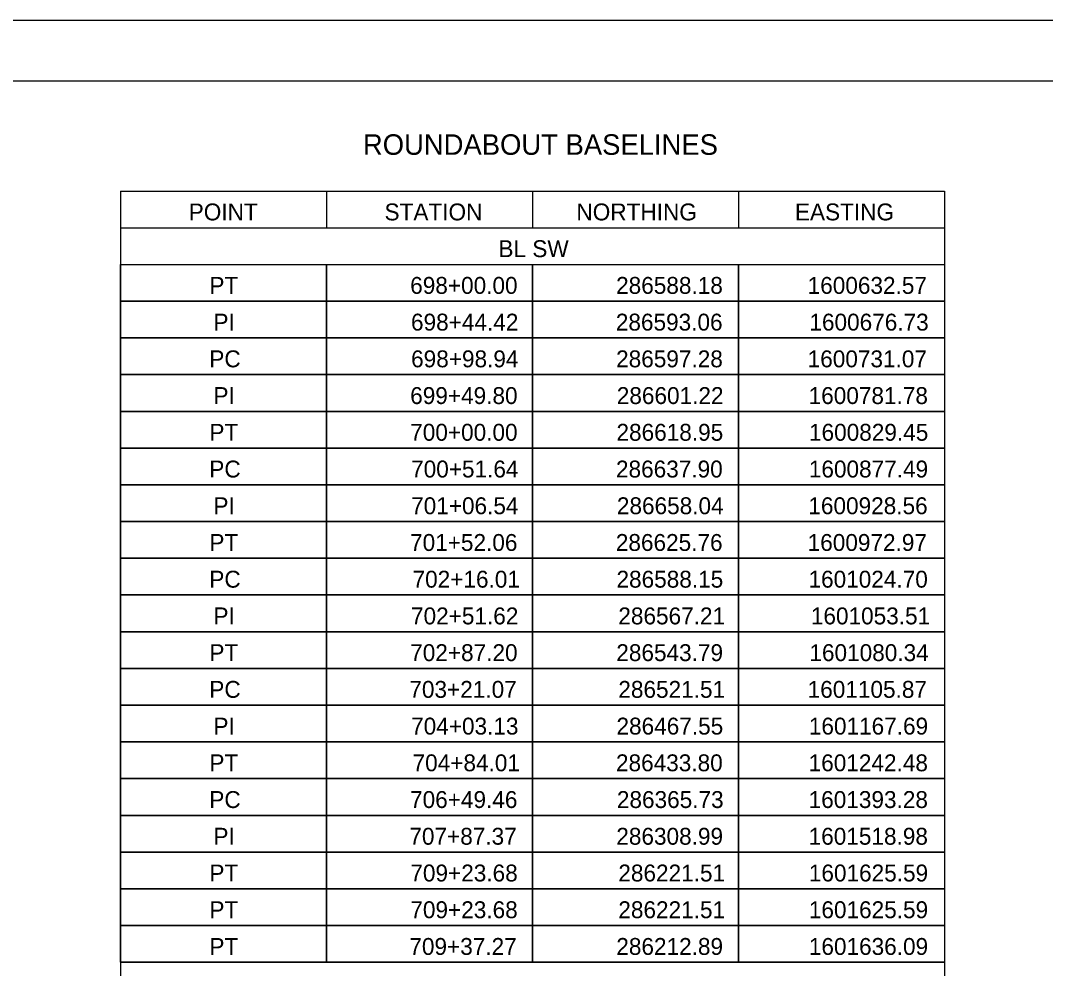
# Model space of a CAD drawing. Extents: x 0 to 34, y 0 to 22.
# Drawn here: x 8.5 to 17, y 14.14 to 22 of the extents above; entities that cross this region are included whole.
import ezdxf

# ---------------------------------------------------------------- set-up
doc = ezdxf.new("R2010")
doc.units = 0
for name, color, linetype in [('SH_Border', 7, 'Continuous'), ('SH_Cut_Line', 7, 'Continuous'), ('SH_Text', 7, 'Continuous')]:
    doc.layers.add(name, color=color, linetype=linetype)

msp = doc.modelspace()

# ---------------------------------------------------------------- linework, layer by layer
at = {"layer": 'SH_Border'}
msp.add_lwpolyline([(1.5, 21.5), (33.5, 21.5), (33.5, 0.5), (1.5, 0.5)], close=True, dxfattribs=at)
at = {"layer": 'SH_Cut_Line'}
msp.add_lwpolyline([(0, 0), (34, 0), (34, 22), (0, 22)], close=True, dxfattribs=at)
at = {"layer": 'SH_Text'}
for p, q in [((9.3309, 20.587), (16.1618, 20.587)), ((9.3309, 20.587), (9.3309, 19.0652)), ((11.0386, 20.587), (11.0386, 20.2826)), ((12.7464, 20.587), (12.7464, 20.2826)), ((14.4541, 20.587), (14.4541, 20.2826)), ((16.1618, 20.587), (16.1618, 19.0652)), ((9.3309, 20.2826), (16.1618, 20.2826)), ((9.3309, 19.9783), (16.1618, 19.9783)), ((11.0386, 19.9783), (11.0386, 19.0652)), ((12.7464, 19.9783), (12.7464, 19.0652)), ((14.4541, 19.9783), (14.4541, 19.0652)), ((9.3309, 19.6739), (16.1618, 19.6739)), ((9.3309, 19.3696), (16.1618, 19.3696)), ((9.3309, 19.0652), (16.1618, 19.0652)), ((9.3309, 19.0652), (9.3309, 18.7609)), ((11.0386, 19.0652), (11.0386, 18.7609)), ((12.7464, 19.0652), (12.7464, 18.7609)), ((14.4541, 19.0652), (14.4541, 18.7609)), ((16.1618, 19.0652), (16.1618, 18.7609)), ((9.3309, 18.7609), (16.1618, 18.7609)), ((9.3309, 18.7609), (9.3309, 18.1522)), ((11.0386, 18.7609), (11.0386, 18.1522)), ((12.7464, 18.7609), (12.7464, 18.1522)), ((14.4541, 18.7609), (14.4541, 18.1522)), ((16.1618, 18.7609), (16.1618, 18.1522)), ((9.3309, 18.4565), (16.1618, 18.4565)), ((9.3309, 18.1522), (16.1618, 18.1522)), ((9.3309, 18.1522), (9.3309, 17.8478)), ((11.0386, 18.1522), (11.0386, 17.8478)), ((12.7464, 18.1522), (12.7464, 17.8478)), ((14.4541, 18.1522), (14.4541, 17.8478)), ((16.1618, 18.1522), (16.1618, 17.8478)), ((9.3309, 17.8478), (16.1618, 17.8478)), ((9.3309, 17.8478), (9.3309, 17.2391)), ((11.0386, 17.8478), (11.0386, 17.2391)), ((12.7464, 17.8478), (12.7464, 17.2391)), ((14.4541, 17.8478), (14.4541, 17.2391)), ((16.1618, 17.8478), (16.1618, 17.2391)), ((9.3309, 17.5435), (16.1618, 17.5435)), ((9.3309, 17.2391), (16.1618, 17.2391)), ((9.3309, 17.2391), (9.3309, 16.9348)), ((11.0386, 17.2391), (11.0386, 16.9348)), ((12.7464, 17.2391), (12.7464, 16.9348)), ((14.4541, 17.2391), (14.4541, 16.9348)), ((16.1618, 17.2391), (16.1618, 16.9348)), ((9.3309, 16.9348), (16.1618, 16.9348)), ((9.3309, 16.9348), (9.3309, 16.3261)), ((11.0386, 16.9348), (11.0386, 16.3261)), ((12.7464, 16.9348), (12.7464, 16.3261)), ((14.4541, 16.9348), (14.4541, 16.3261)), ((16.1618, 16.9348), (16.1618, 16.3261)), ((9.3309, 16.6304), (16.1618, 16.6304)), ((9.3309, 16.3261), (16.1618, 16.3261)), ((9.3309, 16.3261), (9.3309, 16.0217)), ((11.0386, 16.3261), (11.0386, 16.0217)), ((12.7464, 16.3261), (12.7464, 16.0217)), ((14.4541, 16.3261), (14.4541, 16.0217)), ((16.1618, 16.3261), (16.1618, 16.0217)), ((9.3309, 16.0217), (16.1618, 16.0217)), ((9.3309, 16.0217), (9.3309, 15.413)), ((11.0386, 16.0217), (11.0386, 15.413)), ((12.7464, 16.0217), (12.7464, 15.413)), ((14.4541, 16.0217), (14.4541, 15.413)), ((16.1618, 16.0217), (16.1618, 15.413)), ((9.3309, 15.7174), (16.1618, 15.7174)), ((9.3309, 15.413), (16.1618, 15.413)), ((9.3309, 15.413), (9.3309, 15.1087)), ((11.0386, 15.413), (11.0386, 15.1087)), ((12.7464, 15.413), (12.7464, 15.1087)), ((14.4541, 15.413), (14.4541, 15.1087)), ((16.1618, 15.413), (16.1618, 15.1087)), ((9.3309, 15.1087), (16.1618, 15.1087)), ((9.3309, 15.1087), (9.3309, 13.2826)), ((11.0386, 15.1087), (11.0386, 14.1957)), ((12.7464, 15.1087), (12.7464, 14.1957)), ((14.4541, 15.1087), (14.4541, 14.1957)), ((16.1618, 15.1087), (16.1618, 13.2826)), ((9.3309, 14.8043), (16.1618, 14.8043)), ((9.3309, 14.5), (16.1618, 14.5)), ((9.3309, 14.1957), (16.1618, 14.1957))]:
    msp.add_line(p, q, dxfattribs=at)
for points in [[(9.3309, 19.9783), (11.0386, 19.9783), (11.0386, 19.6739), (9.3309, 19.6739)], [(11.0386, 19.9783), (12.7464, 19.9783), (12.7464, 19.6739), (11.0386, 19.6739)], [(12.7464, 19.9783), (14.4541, 19.9783), (14.4541, 19.6739), (12.7464, 19.6739)], [(14.4541, 19.9783), (16.1618, 19.9783), (16.1618, 19.6739), (14.4541, 19.6739)], [(9.3309, 19.6739), (11.0386, 19.6739), (11.0386, 19.3696), (9.3309, 19.3696)], [(11.0386, 19.6739), (12.7464, 19.6739), (12.7464, 19.3696), (11.0386, 19.3696)], [(12.7464, 19.6739), (14.4541, 19.6739), (14.4541, 19.3696), (12.7464, 19.3696)], [(14.4541, 19.6739), (16.1618, 19.6739), (16.1618, 19.3696), (14.4541, 19.3696)], [(9.3309, 19.3696), (11.0386, 19.3696), (11.0386, 19.0652), (9.3309, 19.0652)], [(11.0386, 19.3696), (12.7464, 19.3696), (12.7464, 19.0652), (11.0386, 19.0652)], [(12.7464, 19.3696), (14.4541, 19.3696), (14.4541, 19.0652), (12.7464, 19.0652)], [(14.4541, 19.3696), (16.1618, 19.3696), (16.1618, 19.0652), (14.4541, 19.0652)], [(9.3309, 19.0652), (11.0386, 19.0652), (11.0386, 18.7609), (9.3309, 18.7609)], [(11.0386, 19.0652), (12.7464, 19.0652), (12.7464, 18.7609), (11.0386, 18.7609)], [(12.7464, 19.0652), (14.4541, 19.0652), (14.4541, 18.7609), (12.7464, 18.7609)], [(14.4541, 19.0652), (16.1618, 19.0652), (16.1618, 18.7609), (14.4541, 18.7609)], [(9.3309, 18.7609), (11.0386, 18.7609), (11.0386, 18.4565), (9.3309, 18.4565)], [(11.0386, 18.7609), (12.7464, 18.7609), (12.7464, 18.4565), (11.0386, 18.4565)], [(12.7464, 18.7609), (14.4541, 18.7609), (14.4541, 18.4565), (12.7464, 18.4565)], [(14.4541, 18.7609), (16.1618, 18.7609), (16.1618, 18.4565), (14.4541, 18.4565)], [(9.3309, 18.4565), (11.0386, 18.4565), (11.0386, 18.1522), (9.3309, 18.1522)], [(11.0386, 18.4565), (12.7464, 18.4565), (12.7464, 18.1522), (11.0386, 18.1522)], [(12.7464, 18.4565), (14.4541, 18.4565), (14.4541, 18.1522), (12.7464, 18.1522)], [(14.4541, 18.4565), (16.1618, 18.4565), (16.1618, 18.1522), (14.4541, 18.1522)], [(9.3309, 18.1522), (11.0386, 18.1522), (11.0386, 17.8478), (9.3309, 17.8478)], [(11.0386, 18.1522), (12.7464, 18.1522), (12.7464, 17.8478), (11.0386, 17.8478)], [(12.7464, 18.1522), (14.4541, 18.1522), (14.4541, 17.8478), (12.7464, 17.8478)], [(14.4541, 18.1522), (16.1618, 18.1522), (16.1618, 17.8478), (14.4541, 17.8478)], [(9.3309, 17.8478), (11.0386, 17.8478), (11.0386, 17.5435), (9.3309, 17.5435)], [(11.0386, 17.8478), (12.7464, 17.8478), (12.7464, 17.5435), (11.0386, 17.5435)], [(12.7464, 17.8478), (14.4541, 17.8478), (14.4541, 17.5435), (12.7464, 17.5435)], [(14.4541, 17.8478), (16.1618, 17.8478), (16.1618, 17.5435), (14.4541, 17.5435)], [(9.3309, 17.5435), (11.0386, 17.5435), (11.0386, 17.2391), (9.3309, 17.2391)], [(11.0386, 17.5435), (12.7464, 17.5435), (12.7464, 17.2391), (11.0386, 17.2391)], [(12.7464, 17.5435), (14.4541, 17.5435), (14.4541, 17.2391), (12.7464, 17.2391)], [(14.4541, 17.5435), (16.1618, 17.5435), (16.1618, 17.2391), (14.4541, 17.2391)], [(9.3309, 17.2391), (11.0386, 17.2391), (11.0386, 16.9348), (9.3309, 16.9348)], [(11.0386, 17.2391), (12.7464, 17.2391), (12.7464, 16.9348), (11.0386, 16.9348)], [(12.7464, 17.2391), (14.4541, 17.2391), (14.4541, 16.9348), (12.7464, 16.9348)], [(14.4541, 17.2391), (16.1618, 17.2391), (16.1618, 16.9348), (14.4541, 16.9348)], [(9.3309, 16.9348), (11.0386, 16.9348), (11.0386, 16.6304), (9.3309, 16.6304)], [(11.0386, 16.9348), (12.7464, 16.9348), (12.7464, 16.6304), (11.0386, 16.6304)], [(12.7464, 16.9348), (14.4541, 16.9348), (14.4541, 16.6304), (12.7464, 16.6304)], [(14.4541, 16.9348), (16.1618, 16.9348), (16.1618, 16.6304), (14.4541, 16.6304)], [(9.3309, 16.6304), (11.0386, 16.6304), (11.0386, 16.3261), (9.3309, 16.3261)], [(11.0386, 16.6304), (12.7464, 16.6304), (12.7464, 16.3261), (11.0386, 16.3261)], [(12.7464, 16.6304), (14.4541, 16.6304), (14.4541, 16.3261), (12.7464, 16.3261)], [(14.4541, 16.6304), (16.1618, 16.6304), (16.1618, 16.3261), (14.4541, 16.3261)], [(9.3309, 16.3261), (11.0386, 16.3261), (11.0386, 16.0217), (9.3309, 16.0217)], [(11.0386, 16.3261), (12.7464, 16.3261), (12.7464, 16.0217), (11.0386, 16.0217)], [(12.7464, 16.3261), (14.4541, 16.3261), (14.4541, 16.0217), (12.7464, 16.0217)], [(14.4541, 16.3261), (16.1618, 16.3261), (16.1618, 16.0217), (14.4541, 16.0217)], [(9.3309, 16.0217), (11.0386, 16.0217), (11.0386, 15.7174), (9.3309, 15.7174)], [(11.0386, 16.0217), (12.7464, 16.0217), (12.7464, 15.7174), (11.0386, 15.7174)], [(12.7464, 16.0217), (14.4541, 16.0217), (14.4541, 15.7174), (12.7464, 15.7174)], [(14.4541, 16.0217), (16.1618, 16.0217), (16.1618, 15.7174), (14.4541, 15.7174)], [(9.3309, 15.7174), (11.0386, 15.7174), (11.0386, 15.413), (9.3309, 15.413)], [(11.0386, 15.7174), (12.7464, 15.7174), (12.7464, 15.413), (11.0386, 15.413)], [(12.7464, 15.7174), (14.4541, 15.7174), (14.4541, 15.413), (12.7464, 15.413)], [(14.4541, 15.7174), (16.1618, 15.7174), (16.1618, 15.413), (14.4541, 15.413)], [(9.3309, 15.413), (11.0386, 15.413), (11.0386, 15.1087), (9.3309, 15.1087)], [(11.0386, 15.413), (12.7464, 15.413), (12.7464, 15.1087), (11.0386, 15.1087)], [(12.7464, 15.413), (14.4541, 15.413), (14.4541, 15.1087), (12.7464, 15.1087)], [(14.4541, 15.413), (16.1618, 15.413), (16.1618, 15.1087), (14.4541, 15.1087)], [(9.3309, 15.1087), (11.0386, 15.1087), (11.0386, 14.8043), (9.3309, 14.8043)], [(11.0386, 15.1087), (12.7464, 15.1087), (12.7464, 14.8043), (11.0386, 14.8043)], [(12.7464, 15.1087), (14.4541, 15.1087), (14.4541, 14.8043), (12.7464, 14.8043)], [(14.4541, 15.1087), (16.1618, 15.1087), (16.1618, 14.8043), (14.4541, 14.8043)], [(9.3309, 14.8043), (11.0386, 14.8043), (11.0386, 14.5), (9.3309, 14.5)], [(11.0386, 14.8043), (12.7464, 14.8043), (12.7464, 14.5), (11.0386, 14.5)], [(12.7464, 14.8043), (14.4541, 14.8043), (14.4541, 14.5), (12.7464, 14.5)], [(14.4541, 14.8043), (16.1618, 14.8043), (16.1618, 14.5), (14.4541, 14.5)], [(9.3309, 14.5), (11.0386, 14.5), (11.0386, 14.1957), (9.3309, 14.1957)], [(11.0386, 14.5), (12.7464, 14.5), (12.7464, 14.1957), (11.0386, 14.1957)], [(12.7464, 14.5), (14.4541, 14.5), (14.4541, 14.1957), (12.7464, 14.1957)], [(14.4541, 14.5), (16.1618, 14.5), (16.1618, 14.1957), (14.4541, 14.1957)]]:
    msp.add_lwpolyline(points, close=True, dxfattribs=at)

# ---------------------------------------------------------------- texts
for s, height, p in [('ROUNDABOUT BASELINES', 0.17, (11.3396, 20.887)), ('POINT', 0.14, (9.8953, 20.3435)), ('STATION', 0.14, (11.5187, 20.3435)), ('NORTHING', 0.14, (13.1095, 20.3435)), ('EASTING', 0.14, (14.9208, 20.3435)), ('BL SW', 0.14, (12.4628, 20.0391)), ('PT', 0.14, (10.0668, 19.7348)), ('698+00.00', 0.14, (11.7315, 19.7348)), ('286588.18', 0.14, (13.4385, 19.7348)), ('1600632.57', 0.14, (15.0264, 19.7348)), ('PI', 0.14, (10.1005, 19.4304)), ('698+44.42', 0.14, (11.7382, 19.4304)), ('286593.06', 0.14, (13.4362, 19.4304)), ('1600676.73', 0.14, (15.0409, 19.4304)), ('PC', 0.14, (10.0661, 19.1261)), ('698+98.94', 0.14, (11.739, 19.1261)), ('286597.28', 0.14, (13.4385, 19.1261)), ('1600731.07', 0.14, (15.0264, 19.1261)), ('PI', 0.14, (10.1005, 18.8217)), ('699+49.80', 0.14, (11.7315, 18.8217)), ('286601.22', 0.14, (13.4441, 18.8217)), ('1600781.78', 0.14, (15.0345, 18.8217)), ('PT', 0.14, (10.0668, 18.5174)), ('700+00.00', 0.14, (11.7315, 18.5174)), ('286618.95', 0.14, (13.4416, 18.5174)), ('1600829.45', 0.14, (15.0376, 18.5174)), ('PC', 0.14, (10.0661, 18.213)), ('700+51.64', 0.14, (11.739, 18.213)), ('286637.90', 0.14, (13.4374, 18.213)), ('1600877.49', 0.14, (15.0361, 18.213)), ('PI', 0.14, (10.1005, 17.9087)), ('701+06.54', 0.14, (11.739, 17.9087)), ('286658.04', 0.14, (13.4449, 17.9087)), ('1600928.56', 0.14, (15.0322, 17.9087)), ('PT', 0.14, (10.0668, 17.6043)), ('701+52.06', 0.14, (11.7303, 17.6043)), ('286625.76', 0.14, (13.4362, 17.6043)), ('1600972.97', 0.14, (15.0264, 17.6043)), ('PC', 0.14, (10.0661, 17.3)), ('702+16.01', 0.14, (11.7511, 17.3)), ('286588.15', 0.14, (13.4416, 17.3)), ('1601024.70', 0.14, (15.0334, 17.3)), ('PI', 0.14, (10.1005, 16.9957)), ('702+51.62', 0.14, (11.7382, 16.9957)), ('286567.21', 0.14, (13.457, 16.9957)), ('1601053.51', 0.14, (15.0529, 16.9957)), ('PT', 0.14, (10.0668, 16.6913)), ('702+87.20', 0.14, (11.7315, 16.6913)), ('286543.79', 0.14, (13.4401, 16.6913)), ('1601080.34', 0.14, (15.0409, 16.6913)), ('PC', 0.14, (10.0661, 16.387)), ('703+21.07', 0.14, (11.7245, 16.387)), ('286521.51', 0.14, (13.457, 16.387)), ('1601105.87', 0.14, (15.0264, 16.387)), ('PI', 0.14, (10.1005, 16.0826)), ('704+03.13', 0.14, (11.739, 16.0826)), ('286467.55', 0.14, (13.4416, 16.0826)), ('1601167.69', 0.14, (15.0361, 16.0826)), ('PT', 0.14, (10.0668, 15.7783)), ('704+84.01', 0.14, (11.7511, 15.7783)), ('286433.80', 0.14, (13.4374, 15.7783)), ('1601242.48', 0.14, (15.0345, 15.7783)), ('PC', 0.14, (10.0661, 15.4739)), ('706+49.46', 0.14, (11.7303, 15.4739)), ('286365.73', 0.14, (13.4449, 15.4739)), ('1601393.28', 0.14, (15.0345, 15.4739)), ('PI', 0.14, (10.1005, 15.1696)), ('707+87.37', 0.14, (11.7245, 15.1696)), ('286308.99', 0.14, (13.4401, 15.1696)), ('1601518.98', 0.14, (15.0345, 15.1696)), ('PT', 0.14, (10.0668, 14.8652)), ('709+23.68', 0.14, (11.7327, 14.8652)), ('286221.51', 0.14, (13.457, 14.8652)), ('1601625.59', 0.14, (15.0361, 14.8652)), ('PT', 0.14, (10.0668, 14.5609)), ('709+23.68', 0.14, (11.7327, 14.5609)), ('286221.51', 0.14, (13.457, 14.5609)), ('1601625.59', 0.14, (15.0361, 14.5609)), ('PT', 0.14, (10.0668, 14.2565)), ('709+37.27', 0.14, (11.7245, 14.2565)), ('286212.89', 0.14, (13.4401, 14.2565)), ('1601636.09', 0.14, (15.0361, 14.2565))]:
    msp.add_text(s, height=height, dxfattribs=at).set_placement(p)

doc.saveas('drawing.dxf')
